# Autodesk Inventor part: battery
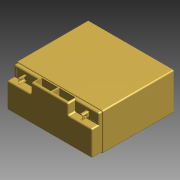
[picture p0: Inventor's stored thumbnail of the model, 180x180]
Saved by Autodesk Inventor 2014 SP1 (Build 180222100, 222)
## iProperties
Created: 2002-01
Part Number: battery
Material: Generic
Document SubType Name: Modeling
Surface Area: 1206.44 cm^2
Volume: 2161.07 cm^3
Appearance: Default
Control State: 0
Master: False
Checked Out: False
Shininess: 0.0
Density: 0.0
Volumn: 0.0
Area: 0.0
PropertySet Name: Model Information
Author: Administrator
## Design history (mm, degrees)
node "Base1"
body "Solid1"
